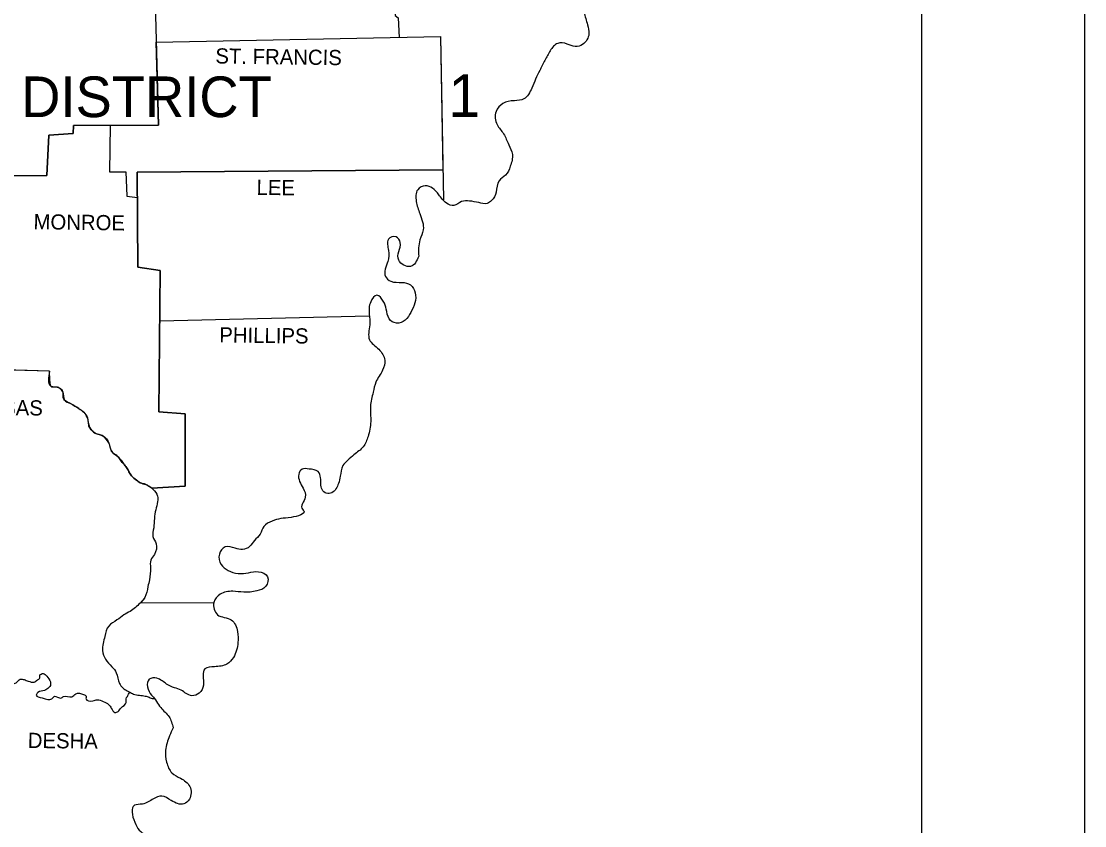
# Model space of a CAD drawing. Extents: x -0.96 to 2.36, y -0.12 to 0.92.
# Drawn here: x 1.2805 to 1.4167, y 0.624 to 0.727 of the extents above; entities that cross this region are included whole.
import ezdxf

# ---------------------------------------------------------------- set-up
doc = ezdxf.new("R2010")
doc.units = 0
for name, color, linetype in [('Level 49', 7, 'Continuous'), ('SHET_Annotations', 7, 'Continuous'), ('SHET_Border-Lines', 7, 'Continuous')]:
    doc.layers.add(name, color=color, linetype=linetype)

msp = doc.modelspace()

# ---------------------------------------------------------------- linework, layer by layer
at = {"layer": 'Level 49'}
for p, q in [((1.33419, 0.72502), (1.3345, 0.70793)), ((1.28416, 0.68218), (1.27942, 0.68231))]:
    msp.add_line(p, q, dxfattribs=at)
for points in [[(1.27948, 0.7072), (1.2838, 0.70723), (1.28406, 0.71239), (1.2872, 0.7126), (1.28725, 0.71361), (1.29812, 0.71366), (1.29782, 0.72429)], [(1.29782, 0.72429), (1.33419, 0.72502)], [(1.3345, 0.70793), (1.29539, 0.70767), (1.29547, 0.69548), (1.29832, 0.69507), (1.29814, 0.67696), (1.30151, 0.6767), (1.30154, 0.66747), (1.29727, 0.66719)]]:
    msp.add_lwpolyline(points, dxfattribs=at)
msp.add_spline([(1.29726, 0.66719), (1.29689, 0.66746), (1.29669, 0.66756), (1.29649, 0.66766), (1.2963, 0.66773), (1.29612, 0.66777), (1.29593, 0.66782), (1.29576, 0.66789), (1.2953, 0.66821), (1.29466, 0.66876), (1.29447, 0.66902), (1.29433, 0.6693), (1.29419, 0.66959), (1.29402, 0.66985), (1.29366, 0.67027), (1.29347, 0.6705), (1.29329, 0.67074), (1.29311, 0.67099), (1.29293, 0.67122), (1.29276, 0.67138), (1.29256, 0.6715), (1.29236, 0.67162), (1.2922, 0.67177), (1.29204, 0.67205), (1.29195, 0.67237), (1.29187, 0.6727), (1.29174, 0.673), (1.29101, 0.67387), (1.29077, 0.67399), (1.29051, 0.67406), (1.29025, 0.67412), (1.29, 0.67424), (1.28979, 0.6744), (1.28959, 0.67458), (1.28927, 0.67501), (1.28917, 0.6753), (1.28913, 0.67561), (1.28909, 0.67591), (1.289, 0.6762), (1.28891, 0.6764), (1.28881, 0.67659), (1.28869, 0.67677), (1.28854, 0.67693), (1.28839, 0.67705), (1.28823, 0.67717), (1.28791, 0.67738), (1.28686, 0.67802), (1.28608, 0.67848), (1.28594, 0.67868), (1.28592, 0.67896), (1.28592, 0.67926), (1.28585, 0.67953), (1.2854, 0.68003), (1.28527, 0.6801), (1.28511, 0.68012), (1.28477, 0.68012), (1.28446, 0.68014), (1.28436, 0.6802), (1.2843, 0.68031), (1.28426, 0.68054), (1.28423, 0.68077), (1.28419, 0.68124), (1.28416, 0.68218)], degree=3, dxfattribs=at)
at = {"layer": 'SHET_Annotations'}
for p, q in [((1.2958, 0.65251), (1.3052, 0.65256)), ((1.2958, 0.65251), (1.3052, 0.65256)), ((1.29742, 0.64027), (1.29756, 0.64027))]:
    msp.add_line(p, q, dxfattribs=at)
for points in [[(1.32812, 0.74545), (1.32838, 0.72769), (1.32877, 0.72741), (1.32893, 0.72491)], [(1.29742, 0.73864), (1.29812, 0.71366), (1.28725, 0.71361), (1.2872, 0.7126), (1.28406, 0.71239), (1.2838, 0.70723), (1.27948, 0.7072)], [(1.29782, 0.72429), (1.33419, 0.72502)], [(1.33419, 0.72502), (1.33457, 0.70412)], [(1.29192, 0.71363), (1.29184, 0.7077), (1.29394, 0.7077), (1.29404, 0.70456), (1.29541, 0.7044)], [(1.29192, 0.71363), (1.29184, 0.7077), (1.29394, 0.7077), (1.29404, 0.70456), (1.29541, 0.7044)], [(1.29727, 0.66719), (1.30154, 0.66747), (1.30151, 0.6767), (1.29814, 0.67696), (1.29832, 0.69507), (1.29547, 0.69548), (1.29539, 0.70767), (1.3345, 0.70793)], [(1.29826, 0.68863), (1.32509, 0.68928)], [(1.28416, 0.68218), (1.26689, 0.68267), (1.26679, 0.67704), (1.23188, 0.67691)]]:
    msp.add_lwpolyline(points, dxfattribs=at)
for points in [[(1.35126, 0.74211), (1.35144, 0.74081), (1.35063, 0.73939), (1.35035, 0.73799), (1.3505, 0.73656), (1.34905, 0.73578), (1.34775, 0.73485), (1.34851, 0.73379), (1.34985, 0.73275), (1.35123, 0.732), (1.35208, 0.73119), (1.35234, 0.72935), (1.35258, 0.72813), (1.35302, 0.72652), (1.3532, 0.72536), (1.3524, 0.72401), (1.35144, 0.72372), (1.3504, 0.72406), (1.34921, 0.72414), (1.34825, 0.7232), (1.34757, 0.72196), (1.3469, 0.72066), (1.34638, 0.71957), (1.34589, 0.71841), (1.34488, 0.71703), (1.34366, 0.7168), (1.34218, 0.71644), (1.34132, 0.71542), (1.34145, 0.71374), (1.34228, 0.71257), (1.34293, 0.71117), (1.3434, 0.70993), (1.34314, 0.7084), (1.34252, 0.70726), (1.34171, 0.70656), (1.34132, 0.7051), (1.34075, 0.70401), (1.34018, 0.70365), (1.33909, 0.70375), (1.33792, 0.70396), (1.33691, 0.70388), (1.33593, 0.70337), (1.33497, 0.7037), (1.33398, 0.70477), (1.33318, 0.7056), (1.33225, 0.70591), (1.33129, 0.70541), (1.3311, 0.70391), (1.33155, 0.70235), (1.33199, 0.70025), (1.33157, 0.69901), (1.33142, 0.69688)], [(1.33142, 0.69688), (1.33038, 0.69558), (1.32885, 0.69639), (1.32885, 0.69748), (1.32906, 0.69865), (1.32851, 0.69937), (1.32755, 0.69906), (1.32755, 0.69763), (1.32745, 0.69623), (1.32716, 0.69431), (1.32784, 0.69369), (1.32926, 0.69354), (1.33035, 0.69322), (1.33097, 0.69221), (1.33092, 0.69092), (1.3304, 0.6897), (1.32968, 0.68869), (1.32856, 0.68832), (1.32763, 0.68889), (1.32727, 0.69011), (1.32688, 0.69112), (1.32607, 0.6919), (1.32527, 0.69107), (1.32509, 0.68946), (1.32514, 0.68809), (1.32511, 0.6862), (1.32631, 0.68498), (1.32706, 0.68358), (1.3268, 0.68231), (1.32594, 0.68078), (1.32558, 0.67948), (1.32524, 0.67766), (1.32527, 0.67572), (1.32493, 0.6738), (1.32431, 0.6725), (1.32312, 0.67147), (1.32234, 0.67079), (1.32172, 0.67009), (1.32138, 0.66872), (1.32115, 0.66778), (1.32029, 0.66662), (1.31959, 0.66654), (1.31904, 0.66701), (1.31889, 0.66778), (1.31886, 0.66854), (1.31853, 0.66931), (1.31738, 0.66965), (1.31648, 0.66962), (1.31606, 0.66898), (1.31663, 0.66719), (1.31689, 0.66605), (1.31653, 0.66449), (1.31671, 0.66431), (1.3151, 0.66345), (1.31375, 0.6633), (1.31266, 0.66299), (1.3116, 0.66229), (1.31111, 0.6613), (1.31038, 0.6605), (1.30976, 0.65972), (1.30888, 0.65935), (1.30792, 0.65951), (1.30665, 0.65967), (1.3059, 0.65876), (1.30613, 0.65744), (1.30701, 0.65666), (1.30831, 0.65629), (1.30963, 0.65637), (1.3109, 0.6565), (1.31207, 0.65585), (1.31184, 0.65463), (1.31069, 0.65404), (1.30901, 0.65388), (1.30763, 0.65399), (1.306, 0.65362), (1.3052, 0.65256), (1.30566, 0.651), (1.30743, 0.65033), (1.30823, 0.64883), (1.30828, 0.64743), (1.30769, 0.64553), (1.30686, 0.64468), (1.30527, 0.64434), (1.30405, 0.64408), (1.30385, 0.64198), (1.30333, 0.64097), (1.30237, 0.64063), (1.30099, 0.64133), (1.30016, 0.64164), (1.29915, 0.64211), (1.29791, 0.64286), (1.29692, 0.64273), (1.29721, 0.64071), (1.29729, 0.64063), (1.2984, 0.6391), (1.29946, 0.63793), (1.29998, 0.63653)], [(1.28416, 0.68218), (1.2843, 0.68031), (1.2854, 0.68003), (1.28585, 0.67953), (1.28608, 0.67848), (1.28686, 0.67802), (1.28791, 0.67738), (1.28854, 0.67693), (1.289, 0.6762), (1.28927, 0.67501), (1.29, 0.67424), (1.29101, 0.67387), (1.29174, 0.673), (1.2922, 0.67177), (1.29293, 0.67122), (1.29366, 0.67027), (1.29402, 0.66985), (1.29466, 0.66876), (1.2953, 0.66821), (1.29576, 0.66789), (1.29649, 0.66766), (1.2974, 0.66707), (1.29799, 0.66616), (1.29799, 0.66547), (1.29776, 0.66442), (1.29758, 0.66333), (1.29749, 0.6621), (1.2974, 0.661), (1.29781, 0.66009), (1.29758, 0.65872), (1.29712, 0.65799), (1.29708, 0.65698), (1.29694, 0.65548), (1.29676, 0.65461), (1.29635, 0.6532), (1.2958, 0.65251)], [(1.28416, 0.68218), (1.2843, 0.68031), (1.2854, 0.68003), (1.28585, 0.67953), (1.28608, 0.67848), (1.28686, 0.67802), (1.28791, 0.67738), (1.28854, 0.67693), (1.289, 0.6762), (1.28927, 0.67501), (1.29, 0.67424), (1.29101, 0.67387), (1.29174, 0.673), (1.2922, 0.67177), (1.29293, 0.67122), (1.29366, 0.67027), (1.29402, 0.66985), (1.29466, 0.66876), (1.2953, 0.66821), (1.29576, 0.66789), (1.29649, 0.66766), (1.2974, 0.66707), (1.29799, 0.66616), (1.29799, 0.66547), (1.29776, 0.66442), (1.29758, 0.66333), (1.29749, 0.6621), (1.2974, 0.661), (1.29781, 0.66009), (1.29758, 0.65872), (1.29712, 0.65799), (1.29708, 0.65698), (1.29694, 0.65548), (1.29676, 0.65461), (1.29635, 0.6532), (1.29576, 0.65247)], [(1.26679, 0.6586), (1.26751, 0.65814), (1.26847, 0.65819), (1.26907, 0.65845), (1.26961, 0.65842), (1.27026, 0.65801), (1.27076, 0.65749), (1.27107, 0.65707), (1.27127, 0.6564), (1.27127, 0.65583), (1.27151, 0.655), (1.27179, 0.65466), (1.27213, 0.65409), (1.27239, 0.65352), (1.27249, 0.65318), (1.27301, 0.65256), (1.27348, 0.65264), (1.27387, 0.65256), (1.27444, 0.65225), (1.27524, 0.65163), (1.2754, 0.65142), (1.27592, 0.65025), (1.27602, 0.64953), (1.2761, 0.64857), (1.27628, 0.64766), (1.27667, 0.64665), (1.27685, 0.64597), (1.27726, 0.64501), (1.27755, 0.64436), (1.27791, 0.64356), (1.27843, 0.64263), (1.27869, 0.64208), (1.27947, 0.64213), (1.27999, 0.64237), (1.2804, 0.64273), (1.28092, 0.64268), (1.28144, 0.6425), (1.28219, 0.64237), (1.28263, 0.64265), (1.28289, 0.64283), (1.28292, 0.64322), (1.28333, 0.64346), (1.2838, 0.64312), (1.28427, 0.64239), (1.28427, 0.64195), (1.28409, 0.64167), (1.28351, 0.6413), (1.28268, 0.64105), (1.28245, 0.64071), (1.28323, 0.64035), (1.28445, 0.64024), (1.28479, 0.64055), (1.28562, 0.64032), (1.28593, 0.64053), (1.28702, 0.6405), (1.28753, 0.64086), (1.28852, 0.64079), (1.28883, 0.64058), (1.28883, 0.64019), (1.28969, 0.63998), (1.29028, 0.64011), (1.29104, 0.63988), (1.29171, 0.63952), (1.29207, 0.63902), (1.29254, 0.63848), (1.29295, 0.63861), (1.29329, 0.63905), (1.29397, 0.63977), (1.29397, 0.64022), (1.29412, 0.64053), (1.29443, 0.6411)], [(1.29576, 0.65247), (1.29448, 0.65142), (1.29366, 0.65096), (1.29279, 0.65032), (1.29174, 0.64955), (1.29124, 0.64822), (1.29096, 0.6464), (1.29133, 0.6453), (1.29215, 0.64434), (1.2927, 0.64357), (1.29311, 0.6422), (1.29411, 0.64124), (1.29443, 0.6411)], [(1.29443, 0.6411), (1.2949, 0.64084), (1.29568, 0.64068), (1.2964, 0.64058), (1.29692, 0.64042), (1.29716, 0.64032), (1.29742, 0.64027)], [(1.29998, 0.63653), (1.29952, 0.63547), (1.29902, 0.63365), (1.29915, 0.6321), (1.29983, 0.63075), (1.30094, 0.63005), (1.30211, 0.62901), (1.30206, 0.62738), (1.30136, 0.62678), (1.29975, 0.6272), (1.29853, 0.62777), (1.29747, 0.62743), (1.29604, 0.62676), (1.29503, 0.6266), (1.29506, 0.62445), (1.29646, 0.62287), (1.2977, 0.62287), (1.29913, 0.62271), (1.29962, 0.62105), (1.29879, 0.6197), (1.29742, 0.61898), (1.2957, 0.61981), (1.29449, 0.62069), (1.29321, 0.62152), (1.29168, 0.62193), (1.2908, 0.62175), (1.29041, 0.61983), (1.29114, 0.61809), (1.29233, 0.61687), (1.29342, 0.61534), (1.29324, 0.6142), (1.29241, 0.61389), (1.29096, 0.61358), (1.29008, 0.61309), (1.28987, 0.61275), (1.29031, 0.6112), (1.29072, 0.60948), (1.29072, 0.60821), (1.29023, 0.60702), (1.28945, 0.6052), (1.28953, 0.60404), (1.29008, 0.60347), (1.29078, 0.60367), (1.29168, 0.6043), (1.29225, 0.60505), (1.29277, 0.60593), (1.29373, 0.60671), (1.2949, 0.60603), (1.29521, 0.60463), (1.29451, 0.60339), (1.29355, 0.60284), (1.29238, 0.6024), (1.29148, 0.60139), (1.29171, 0.6002), (1.29241, 0.59958), (1.2941, 0.59986), (1.29524, 0.60035), (1.29586, 0.60103), (1.29664, 0.60181), (1.29705, 0.60256), (1.29765, 0.60339), (1.29871, 0.60362), (1.29921, 0.60292), (1.29902, 0.60139), (1.29838, 0.59994), (1.29752, 0.59867), (1.29656, 0.59781), (1.29539, 0.59595), (1.29563, 0.59421), (1.29604, 0.59278), (1.29669, 0.59169), (1.29778, 0.59193), (1.29902, 0.59208), (1.29978, 0.59149), (1.29967, 0.59021), (1.29874, 0.58897), (1.29791, 0.5878), (1.29744, 0.58612), (1.29762, 0.58498), (1.29762, 0.58394), (1.29723, 0.5828), (1.29659, 0.58215), (1.29493, 0.58223), (1.29316, 0.58241), (1.29218, 0.58186), (1.29236, 0.58028), (1.29342, 0.57917), (1.29415, 0.57857), (1.29519, 0.57727), (1.29565, 0.57624), (1.2955, 0.57533), (1.29487, 0.57455), (1.29301, 0.57362)]]:
    msp.add_spline(points, degree=3, dxfattribs=at)
at = {"layer": 'SHET_Border-Lines'}
for points in [[(0, 0), (1.41666, 0), (1.41666, 0.91666), (0, 0.91666)], [(0.04167, 0.02083), (1.39583, 0.02083), (1.39583, 0.89583), (0.04167, 0.89583)]]:
    msp.add_lwpolyline(points, close=True, dxfattribs=at)

# ---------------------------------------------------------------- texts
at = {"layer": 'SHET_Annotations'}
for s, height, rotation, p in [('ST. FRANCIS', 0.0019451, 359.1956, (1.30538, 0.72157)), ('ST. FRANCIS', 0.0019451, 359.1956, (1.30538, 0.72157)), ('LEE', 0.001945, 359.3634, (1.31065, 0.70474)), ('MONROE', 0.001945, 359.1697, (1.2821, 0.70035)), ('PHILLIPS', 0.001945, 359.217, (1.30588, 0.68586)), ('ARKANSAS', 0.001945, 359.2655, (1.26913, 0.67667)), ('DESHA', 0.001945, 359.2949, (1.28137, 0.63394))]:
    msp.add_text(s, height=height, rotation=rotation, dxfattribs=at).set_placement(p)
for s, height, p in [('1', 0.00548, (1.33522, 0.7147)), ('DISTRICT', 0.005203, (1.28053, 0.7147))]:
    msp.add_text(s, height=height, dxfattribs=at).set_placement(p)

doc.saveas('drawing.dxf')
